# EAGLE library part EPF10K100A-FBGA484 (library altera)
EPF10K100 FLEX 10K family
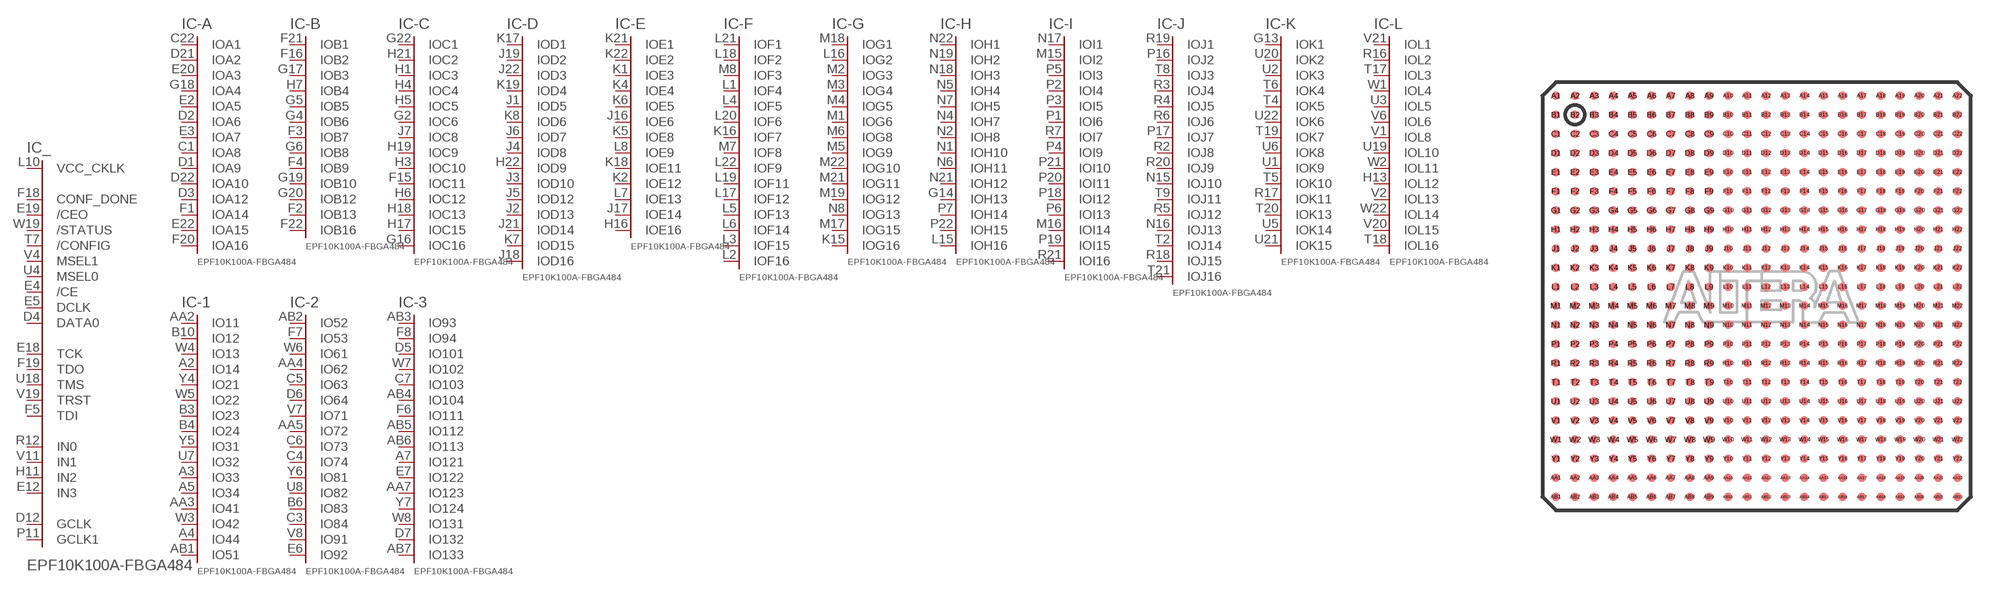
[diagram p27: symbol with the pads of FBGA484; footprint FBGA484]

Designator prefix IC; gates _=100B484C -A=A484 -B=B484 -C=C484 -D=D484 -E=E484 -F=F484 -G=G484 -H=H484 -I=I484 -J=J484 -K=K484 -L=L484 -1=IO51 -2=IO92 -3=IO133 -4=IO173 -5=IO214 -6=IO254 -7=IO302 -8=IO353 -9=IO401 -10=IO443 -11=IO483 -12=IO524 G1=GND G2=GND G3=GND G4=GND G5=GND G6=GND G7=GND G8=GND G9=GND G10=GND G11=GND G12=GND G13=GND G14=GND G15=GND G16=GND G17=GND G18=GND G19=GND G20=GND G21=GND G22=GND G23=GND G24=GND G25=GND G26=GND G27=GND G28=GND G29=GND G30=GND G31=GND G32=GND G33=GND G34=GND G35=GND G36=GND G37=GND G38=GND G39=GND G40=GND G41=GND G42=GND G43=GND G44=GND G45=GND G46=GND G47=GND G48=GND G49=GND V1=VCCINT V2=VCCINT V3=VCCINT V4=VCCINT V5=VCCINT V6=VCCINT V7=VCCINT V8=VCCINT V9=VCCINT V10=VCCINT V11=VCCINT V12=VCCINT V13=VCCINT V14=VCCINT V15=VCCINT V16=VCCINT V17=VCCINT V18=VCCINT V19=VCCINT V20=VCCINT V21=VCCINT V22=VCCINT VO1=VCCIO VO2=VCCIO VO3=VCCIO VO4=VCCIO VO5=VCCIO VO6=VCCIO VO7=VCCIO VO8=VCCIO VO9=VCCIO VO10=VCCIO VO11=VCCIO VO12=VCCIO VO13=VCCIO VO14=VCCIO VO15=VCCIO VO16=VCCIO VO17=VCCIO VO18=VCCIO VO19=VCCIO VO20=VCCIO VO21=VCCIO VO22=VCCIO VO23=VCCIO VO24=VCCIO VO25=VCCIO VO26=VCCIO VO27=VCCIO VO28=VCCIO VO29=VCCIO

## EPF10K100A-FBGA484 (MPN: EPF10K100AFC484-1; OC_FARNELL: unknown; OC_NEWARK: 51R8791)  [FBGA484]
A1  G6:GND  pwr
A2  -1:IO14
A3  -1:IO33
A4  -1:IO44
A5  -1:IO34
A6  VO2:VCCIO  pwr
A7  -3:IO121
A8  G7:GND  pwr
A9  -5:IO194
A10  -6:IO234
A11  -7:IO263
A12  -7:IO284
A13  VO3:VCCIO  pwr
A14  -9:IO363
A15  -9:IO381
A16  -10:IO432
A17  -10:IO434
A18  -10:IO441
A19  -11:IO452
A20  -11:IO471
A21  -12:IO501
A22  G8:GND  pwr
AA1  G1:GND  pwr
AA2  -1:IO11
AA3  -1:IO41
AA4  -2:IO62
AA5  -2:IO72
AA6  G2:GND  pwr
AA7  -3:IO123
AA8  -4:IO153
AA9  -5:IO181
AA10  -6:IO223
AA11  -7:IO264
AA12  V1:VCC  pwr
AA13  -8:IO313
AA14  -8:IO341
AA15  -9:IO394
AA16  -10:IO413
AA17  -11:IO451
AA18  -11:IO481
AA19  -12:IO492
AA20  -12:IO511
AA21  -12:IO513
AA22  G3:GND  pwr
AB1  -1:IO51
AB2  -2:IO52
AB3  -3:IO93
AB4  -3:IO104
AB5  -3:IO112
AB6  -3:IO113
AB7  -3:IO133
AB8  -4:IO151
AB9  -5:IO191
AB10  -6:IO231
AB11  G4:GND  pwr
AB12  -7:IO271
AB13  VO1:VCCIO  pwr
AB14  -8:IO331
AB15  -9:IO373
AB16  G5:GND  pwr
AB17  -10:IO442
AB18  -11:IO463
AB19  -11:IO472
AB20  -11:IO483
AB21  -12:IO504
AB22  -12:IO521
B1  G9:GND  pwr
B2  G10:GND  pwr
B3  -1:IO23
B4  -1:IO24
B5  VO4:VCCIO  pwr
B6  -2:IO83
B7  -4:IO134
B8  -4:IO164
B9  -5:IO192
B10  -1:IO12
B11  -6:IO252
B12  -7:IO282
B13  -8:IO323
B14  -9:IO364
B15  -9:IO371
B16  -10:IO412
B17  G11:GND  pwr
B18  -11:IO461
B19  -12:IO494
B20  -12:IO514
B21  G12:GND  pwr
B22  G13:GND  pwr
C1  -A:IOA8
C2  G14:GND  pwr
C3  -2:IO84
C4  -2:IO74
C5  -2:IO63
C6  -2:IO73
C7  -3:IO103
C8  -4:IO154
C9  -5:IO182
C10  -5:IO212
C11  V2:VCC  pwr
C12  -7:IO274
C13  -8:IO312
C14  -9:IO354
C15  V3:VCC  pwr
C16  -10:IO424
C17  -11:IO444
C18  -11:IO482
C19  -12:IO524
C20  -11:IO464
C21  G15:GND  pwr
C22  -A:IOA1
D1  -A:IOA9
D2  -A:IOA6
D3  -A:IOA12
D4  _:DATA0  in
D5  -3:IO101
D6  -2:IO64
D7  -3:IO132
D8  -4:IO142
D9  -5:IO184
D10  -6:IO221
D11  -6:IO253
D12  _:GCLK  in
D13  -8:IO333
D14  -8:IO353
D15  -9:IO391
D16  -10:IO423
D17  -11:IO474
D18  -12:IO512
D19  -12:IO522
D20  -11:IO454
D21  -A:IOA2
D22  -A:IOA10
E1  VO5:VCCIO  pwr
E2  -A:IOA5
E3  -A:IOA7
E4  _:/CE  in
E5  _:DCLK  in
E6  -2:IO92
E7  -3:IO122
E8  -4:IO152
E9  -5:IO201
E10  -6:IO222
E11  -6:IO242
E12  _:IN3  in
E13  -8:IO344
E14  -9:IO374
E15  -10:IO404
E16  -10:IO411
E17  -12:IO502
E18  _:TCK
E19  _:/CEO  in
E20  -A:IOA3
E21  G16:GND  pwr
E22  -A:IOA15
F1  -A:IOA14
F2  -B:IOB13
F3  -B:IOB7
F4  -B:IOB9
F5  _:TDI
F6  -3:IO111
F7  -2:IO53
F8  -3:IO94
F9  -5:IO174
F10  -5:IO214
F11  -6:IO232
F12  -7:IO272
F13  -8:IO343
F14  -9:IO384
F15  -C:IOC11
F16  -B:IOB2
F17  -12:IO491
F18  _:CONF_DONE  in
F19  _:TDO
F20  -A:IOA16
F21  -B:IOB1
F22  -B:IOB16
G1  VO6:VCCIO  pwr
G2  -C:IOC6
G3  G17:GND  pwr
G4  -B:IOB6
G5  -B:IOB5
G6  -B:IOB8
G7  -4:IO143
G8  -4:IO171
G9  -4:IO162
G10  -6:IO244
G11  -7:IO261
G12  -7:IO294
G13  -K:IOK1
G14  -H:IOH13
G15  VO7:VCCIO  pwr
G16  -C:IOC16
G17  -B:IOB3
G18  -A:IOA4
G19  -B:IOB10
G20  -B:IOB12
G21  G18:GND  pwr
G22  -C:IOC1
H1  -C:IOC3
H2  G19:GND  pwr
H3  -C:IOC10
H4  -C:IOC4
H5  -C:IOC5
H6  -C:IOC12
H7  -B:IOB4
H8  G20:GND  pwr
H9  VO8:VCCIO  pwr
H10  -5:IO204
H11  _:IN2  in
H12  -7:IO302
H13  -L:IOL12
H14  V4:VCC  pwr
H15  G21:GND  pwr
H16  -E:IOE16
H17  -C:IOC15
H18  -C:IOC13
H19  -C:IOC9
H20  VO9:VCCIO  pwr
H21  -C:IOC2
H22  -D:IOD9
J1  -D:IOD5
J2  -D:IOD13
J3  -D:IOD10
J4  -D:IOD8
J5  -D:IOD12
J6  -D:IOD7
J7  -C:IOC8
J8  V5:VCC  pwr
J9  G22:GND  pwr
J10  V6:VCC  pwr
J11  VO10:VCCIO  pwr
J12  V7:VCC  pwr
J13  VO11:VCCIO  pwr
J14  G23:GND  pwr
J15  V8:VCC  pwr
J16  -E:IOE6
J17  -E:IOE14
J18  -D:IOD16
J19  -D:IOD2
J20  G24:GND  pwr
J21  -D:IOD14
J22  -D:IOD3
K1  -E:IOE3
K2  -E:IOE12
K3  G25:GND  pwr
K4  -E:IOE4
K5  -E:IOE8
K6  -E:IOE5
K7  -D:IOD15
K8  -D:IOD6
K9  VO12:VCCIO  pwr
K10  G26:GND  pwr
K11  VO13:VCCIO  pwr
K12  G27:GND  pwr
K13  G28:GND  pwr
K14  VO14:VCCIO  pwr
K15  -G:IOG16
K16  -F:IOF7
K17  -D:IOD1
K18  -E:IOE11
K19  -D:IOD4
K20  VO15:VCCIO  pwr
K21  -E:IOE1
K22  -E:IOE2
L1  -F:IOF4
L2  -F:IOF16
L3  -F:IOF15
L4  -F:IOF5
L5  -F:IOF13
L6  -F:IOF14
L7  -E:IOE13
L8  -E:IOE9
L9  V9:VCC  pwr
L10  _:VCC_CKLK  pas
L11  G29:GND  pwr
L12  G30:GND  pwr
L13  V10:VCC  pwr
L14  VO16:VCCIO  pwr
L15  -H:IOH16
L16  -G:IOG2
L17  -F:IOF12
L18  -F:IOF2
L19  -F:IOF11
L20  -F:IOF6
L21  -F:IOF1
L22  -F:IOF9
M1  -G:IOG6
M2  -G:IOG3
M3  -G:IOG4
M4  -G:IOG5
M5  -G:IOG9
M6  -G:IOG8
M7  -F:IOF8
M8  -F:IOF3
M9  VO17:VCCIO  pwr
M10  V11:VCC  pwr
M11  G31:GND  pwr
M12  G32:GND  pwr
M13  V12:VCC  pwr
M14  V13:VCC  pwr
M15  -I:IOI2
M16  -I:IOI14
M17  -G:IOG15
M18  -G:IOG1
M19  -G:IOG12
M20  G33:GND  pwr
M21  -G:IOG11
M22  -G:IOG10
N1  -H:IOH10
N2  -H:IOH8
N3  VO18:VCCIO  pwr
N4  -H:IOH7
N5  -H:IOH4
N6  -H:IOH11
N7  -H:IOH5
N8  -G:IOG13
N9  VO19:VCCIO  pwr
N10  G34:GND  pwr
N11  VO20:VCCIO  pwr
N12  V14:VCC  pwr
N13  G35:GND  pwr
N14  VO21:VCCIO  pwr
N15  -J:IOJ10
N16  -J:IOJ13
N17  -I:IOI1
N18  -H:IOH3
N19  -H:IOH2
N20  VO22:VCCIO  pwr
N21  -H:IOH12
N22  -H:IOH1
P1  -I:IOI6
P2  -I:IOI4
P3  -I:IOI5
P4  -I:IOI9
P5  -I:IOI3
P6  -I:IOI13
P7  -H:IOH14
P8  V15:VCC  pwr
P9  G36:GND  pwr
P10  V16:VCC  pwr
P11  _:GCLK1  in
P12  V17:VCC  pwr
P13  VO23:VCCIO  pwr
P14  G37:GND  pwr
P15  V18:VCC  pwr
P16  -J:IOJ2
P17  -J:IOJ7
P18  -I:IOI12
P19  -I:IOI15
P20  -I:IOI11
P21  -I:IOI10
P22  -H:IOH15
R1  VO24:VCCIO  pwr
R2  -J:IOJ8
R3  -J:IOJ4
R4  -J:IOJ5
R5  -J:IOJ12
R6  -J:IOJ6
R7  -I:IOI7
R8  G38:GND  pwr
R9  VO25:VCCIO  pwr
R10  -4:IO161
R11  -4:IO173
R12  _:IN0  in
R13  -7:IO281
R14  V19:VCC  pwr
R15  G39:GND  pwr
R16  -L:IOL2
R17  -K:IOK11
R18  -J:IOJ15
R19  -J:IOJ1
R20  -J:IOJ9
R21  -I:IOI16
R22  G40:GND  pwr
T1  G41:GND  pwr
T2  -J:IOJ14
T3  VO26:VCCIO  pwr
T4  -K:IOK5
T5  -K:IOK10
T6  -K:IOK4
T7  _:/CONFIG  in
T8  -J:IOJ3
T9  -J:IOJ11
T10  -4:IO163
T11  -5:IO213
T12  -6:IO233
T13  -8:IO303
T14  -8:IO321
T15  VO27:VCCIO  pwr
T16  -9:IO392
T17  -L:IOL3
T18  -L:IOL16
T19  -K:IOK7
T20  -K:IOK13
T21  -J:IOJ16
T22  VO28:VCCIO  pwr
U1  -K:IOK9
U2  -K:IOK3
U3  -L:IOL5
U4  _:MSEL0  in
U5  -K:IOK14
U6  -K:IOK8
U7  -1:IO32
U8  -2:IO82
U9  -4:IO141
U10  -5:IO203
U11  -6:IO241
U12  -6:IO243
U13  -7:IO293
U14  -8:IO351
U15  -9:IO361
U16  -9:IO401
U17  -11:IO462
U18  _:TMS
U19  -L:IOL10
U20  -K:IOK2
U21  -K:IOK15
U22  -K:IOK6
V1  -L:IOL8
V2  -L:IOL13
V3  G42:GND  pwr
V4  _:MSEL1  in
V5  V20:VCC  pwr
V6  -L:IOL6
V7  -2:IO71
V8  -2:IO91
V9  -4:IO144
V10  -5:IO202
V11  _:IN1  in
V12  -6:IO254
V13  -7:IO291
V14  -8:IO322
V15  -9:IO372
V16  -10:IO402
V17  -10:IO421
V18  -11:IO453
V19  _:TRST
V20  -L:IOL15
V21  -L:IOL1
V22  VO29:VCCIO  pwr
W1  -L:IOL4
W2  -L:IOL11
W3  -1:IO42
W4  -1:IO13
W5  -1:IO22
W6  -2:IO61
W7  -3:IO102
W8  -3:IO131
W9  -5:IO183
W10  -6:IO224
W11  G43:GND  pwr
W12  -7:IO273
W13  -7:IO301
W14  -8:IO332
W15  -9:IO362
W16  -10:IO414
W17  -10:IO431
W18  -11:IO473
W19  _:/STATUS  in
W20  G44:GND  pwr
W21  V21:VCC  pwr
W22  -L:IOL14
Y1  G45:GND  pwr
Y2  G46:GND  pwr
Y3  G47:GND  pwr
Y4  -1:IO21
Y5  -1:IO31
Y6  -2:IO81
Y7  -3:IO124
Y8  V22:VCC  pwr
Y9  -4:IO172
Y10  -5:IO211
Y11  -6:IO251
Y12  -7:IO283
Y13  -8:IO311
Y14  -8:IO352
Y15  -9:IO383
Y16  -10:IO433
Y17  -10:IO443
Y18  -12:IO493
Y19  -12:IO503
Y20  -12:IO523
Y21  G48:GND  pwr
Y22  G49:GND  pwr

## Footprint FBGA484 (pad centres in mm)
Fine Ball Grid Array
smd 0.45 x 0.45: A1 -10.5,10.5; A2 -9.5,10.5; A3 -8.5,10.5; A4 -7.5,10.5; A5 -6.5,10.5; A6 -5.5,10.5; A7 -4.5,10.5; A8 -3.5,10.5; A9 -2.5,10.5; A10 -1.5,10.5; A11 -0.5,10.5; A12 0.5,10.5; A13 1.5,10.5; A14 2.5,10.5; A15 3.5,10.5; A16 4.5,10.5; A17 5.5,10.5; A18 6.5,10.5; A19 7.5,10.5; A20 8.5,10.5; A21 9.5,10.5; A22 10.5,10.5; AA1 -10.5,-9.5; AA2 -9.5,-9.5; AA3 -8.5,-9.5; AA4 -7.5,-9.5; AA5 -6.5,-9.5; AA6 -5.5,-9.5; AA7 -4.5,-9.5; AA8 -3.5,-9.5; AA9 -2.5,-9.5; AA10 -1.5,-9.5; AA11 -0.5,-9.5; AA12 0.5,-9.5; AA13 1.5,-9.5; AA14 2.5,-9.5; AA15 3.5,-9.5; AA16 4.5,-9.5; AA17 5.5,-9.5; AA18 6.5,-9.5; AA19 7.5,-9.5; AA20 8.5,-9.5; AA21 9.5,-9.5; AA22 10.5,-9.5; AB1 -10.5,-10.5; AB2 -9.5,-10.5; AB3 -8.5,-10.5; AB4 -7.5,-10.5; AB5 -6.5,-10.5; AB6 -5.5,-10.5; AB7 -4.5,-10.5; AB8 -3.5,-10.5; AB9 -2.5,-10.5; AB10 -1.5,-10.5; AB11 -0.5,-10.5; AB12 0.5,-10.5; AB13 1.5,-10.5; AB14 2.5,-10.5; AB15 3.5,-10.5; AB16 4.5,-10.5; AB17 5.5,-10.5; AB18 6.5,-10.5; AB19 7.5,-10.5; AB20 8.5,-10.5; AB21 9.5,-10.5; AB22 10.5,-10.5; B1 -10.5,9.5; B2 -9.5,9.5; B3 -8.5,9.5; B4 -7.5,9.5; B5 -6.5,9.5; B6 -5.5,9.5; B7 -4.5,9.5; B8 -3.5,9.5; B9 -2.5,9.5; B10 -1.5,9.5; B11 -0.5,9.5; B12 0.5,9.5; B13 1.5,9.5; B14 2.5,9.5; B15 3.5,9.5; B16 4.5,9.5; B17 5.5,9.5; B18 6.5,9.5; B19 7.5,9.5; B20 8.5,9.5; B21 9.5,9.5; B22 10.5,9.5; C1 -10.5,8.5; C2 -9.5,8.5; C3 -8.5,8.5; C4 -7.5,8.5; C5 -6.5,8.5; C6 -5.5,8.5; C7 -4.5,8.5; C8 -3.5,8.5; C9 -2.5,8.5; C10 -1.5,8.5; C11 -0.5,8.5; C12 0.5,8.5; C13 1.5,8.5; C14 2.5,8.5; C15 3.5,8.5; C16 4.5,8.5; C17 5.5,8.5; C18 6.5,8.5; C19 7.5,8.5; C20 8.5,8.5; C21 9.5,8.5; C22 10.5,8.5; D1 -10.5,7.5; D2 -9.5,7.5; D3 -8.5,7.5; D4 -7.5,7.5; D5 -6.5,7.5; D6 -5.5,7.5; D7 -4.5,7.5; D8 -3.5,7.5; D9 -2.5,7.5; D10 -1.5,7.5; D11 -0.5,7.5; D12 0.5,7.5; D13 1.5,7.5; D14 2.5,7.5; D15 3.5,7.5; D16 4.5,7.5; D17 5.5,7.5; D18 6.5,7.5; D19 7.5,7.5; D20 8.5,7.5; D21 9.5,7.5; D22 10.5,7.5; E1 -10.5,6.5; E2 -9.5,6.5; E3 -8.5,6.5; E4 -7.5,6.5; E5 -6.5,6.5; E6 -5.5,6.5; E7 -4.5,6.5; E8 -3.5,6.5; E9 -2.5,6.5; E10 -1.5,6.5; E11 -0.5,6.5; E12 0.5,6.5; E13 1.5,6.5; E14 2.5,6.5; E15 3.5,6.5; E16 4.5,6.5; E17 5.5,6.5; E18 6.5,6.5; E19 7.5,6.5; E20 8.5,6.5; E21 9.5,6.5; E22 10.5,6.5; F1 -10.5,5.5; F2 -9.5,5.5; F3 -8.5,5.5; F4 -7.5,5.5; F5 -6.5,5.5; F6 -5.5,5.5; F7 -4.5,5.5; F8 -3.5,5.5; F9 -2.5,5.5; F10 -1.5,5.5; F11 -0.5,5.5; F12 0.5,5.5; F13 1.5,5.5; F14 2.5,5.5; F15 3.5,5.5; F16 4.5,5.5; F17 5.5,5.5; F18 6.5,5.5; F19 7.5,5.5; F20 8.5,5.5; F21 9.5,5.5; F22 10.5,5.5; G1 -10.5,4.5; G2 -9.5,4.5; G3 -8.5,4.5; G4 -7.5,4.5; G5 -6.5,4.5; G6 -5.5,4.5; G7 -4.5,4.5; G8 -3.5,4.5; G9 -2.5,4.5; G10 -1.5,4.5; G11 -0.5,4.5; G12 0.5,4.5; G13 1.5,4.5; G14 2.5,4.5; G15 3.5,4.5; G16 4.5,4.5; G17 5.5,4.5; G18 6.5,4.5; G19 7.5,4.5; G20 8.5,4.5; G21 9.5,4.5; G22 10.5,4.5; H1 -10.5,3.5; H2 -9.5,3.5; H3 -8.5,3.5; H4 -7.5,3.5; H5 -6.5,3.5; H6 -5.5,3.5; H7 -4.5,3.5; H8 -3.5,3.5; H9 -2.5,3.5; H10 -1.5,3.5; H11 -0.5,3.5; H12 0.5,3.5; H13 1.5,3.5; H14 2.5,3.5; H15 3.5,3.5; H16 4.5,3.5; H17 5.5,3.5; H18 6.5,3.5; H19 7.5,3.5; H20 8.5,3.5; H21 9.5,3.5; H22 10.5,3.5; J1 -10.5,2.5; J2 -9.5,2.5; J3 -8.5,2.5; J4 -7.5,2.5; J5 -6.5,2.5; J6 -5.5,2.5; J7 -4.5,2.5; J8 -3.5,2.5; J9 -2.5,2.5; J10 -1.5,2.5; J11 -0.5,2.5; J12 0.5,2.5; J13 1.5,2.5; J14 2.5,2.5; J15 3.5,2.5; J16 4.5,2.5; J17 5.5,2.5; J18 6.5,2.5; J19 7.5,2.5; J20 8.5,2.5; J21 9.5,2.5; J22 10.5,2.5; K1 -10.5,1.5; K2 -9.5,1.5; K3 -8.5,1.5; K4 -7.5,1.5; K5 -6.5,1.5; K6 -5.5,1.5; K7 -4.5,1.5; K8 -3.5,1.5; K9 -2.5,1.5; K10 -1.5,1.5; K11 -0.5,1.5; K12 0.5,1.5; K13 1.5,1.5; K14 2.5,1.5; K15 3.5,1.5; K16 4.5,1.5; K17 5.5,1.5; K18 6.5,1.5; K19 7.5,1.5; K20 8.5,1.5; K21 9.5,1.5; K22 10.5,1.5; L1 -10.5,0.5; L2 -9.5,0.5; L3 -8.5,0.5; L4 -7.5,0.5; L5 -6.5,0.5; L6 -5.5,0.5; L7 -4.5,0.5; L8 -3.5,0.5; L9 -2.5,0.5; L10 -1.5,0.5; L11 -0.5,0.5; L12 0.5,0.5; L13 1.5,0.5; L14 2.5,0.5; L15 3.5,0.5; L16 4.5,0.5; L17 5.5,0.5; L18 6.5,0.5; L19 7.5,0.5; L20 8.5,0.5; L21 9.5,0.5; L22 10.5,0.5; M1 -10.5,-0.5; M2 -9.5,-0.5; M3 -8.5,-0.5; M4 -7.5,-0.5; M5 -6.5,-0.5; M6 -5.5,-0.5; M7 -4.5,-0.5; M8 -3.5,-0.5; M9 -2.5,-0.5; M10 -1.5,-0.5; M11 -0.5,-0.5; M12 0.5,-0.5; M13 1.5,-0.5; M14 2.5,-0.5; M15 3.5,-0.5; M16 4.5,-0.5; M17 5.5,-0.5; M18 6.5,-0.5; M19 7.5,-0.5; M20 8.5,-0.5; M21 9.5,-0.5; M22 10.5,-0.5; N1 -10.5,-1.5; N2 -9.5,-1.5; N3 -8.5,-1.5; N4 -7.5,-1.5; N5 -6.5,-1.5; N6 -5.5,-1.5; N7 -4.5,-1.5; N8 -3.5,-1.5; N9 -2.5,-1.5; N10 -1.5,-1.5; N11 -0.5,-1.5; N12 0.5,-1.5; N13 1.5,-1.5; N14 2.5,-1.5; N15 3.5,-1.5; N16 4.5,-1.5; N17 5.5,-1.5; N18 6.5,-1.5; N19 7.5,-1.5; N20 8.5,-1.5; N21 9.5,-1.5; N22 10.5,-1.5; P1 -10.5,-2.5; P2 -9.5,-2.5; P3 -8.5,-2.5; P4 -7.5,-2.5; P5 -6.5,-2.5; P6 -5.5,-2.5; P7 -4.5,-2.5; P8 -3.5,-2.5; P9 -2.5,-2.5; P10 -1.5,-2.5; P11 -0.5,-2.5; P12 0.5,-2.5; P13 1.5,-2.5; P14 2.5,-2.5; P15 3.5,-2.5; P16 4.5,-2.5; P17 5.5,-2.5; P18 6.5,-2.5; P19 7.5,-2.5; P20 8.5,-2.5; P21 9.5,-2.5; P22 10.5,-2.5; R1 -10.5,-3.5; R2 -9.5,-3.5; R3 -8.5,-3.5; R4 -7.5,-3.5; R5 -6.5,-3.5; R6 -5.5,-3.5; R7 -4.5,-3.5; R8 -3.5,-3.5; R9 -2.5,-3.5; R10 -1.5,-3.5; R11 -0.5,-3.5; R12 0.5,-3.5; R13 1.5,-3.5; R14 2.5,-3.5; R15 3.5,-3.5; R16 4.5,-3.5; R17 5.5,-3.5; R18 6.5,-3.5; R19 7.5,-3.5; R20 8.5,-3.5; R21 9.5,-3.5; R22 10.5,-3.5; T1 -10.5,-4.5; T2 -9.5,-4.5; T3 -8.5,-4.5; T4 -7.5,-4.5; T5 -6.5,-4.5; T6 -5.5,-4.5; T7 -4.5,-4.5; T8 -3.5,-4.5; T9 -2.5,-4.5; T10 -1.5,-4.5; T11 -0.5,-4.5; T12 0.5,-4.5; T13 1.5,-4.5; T14 2.5,-4.5; T15 3.5,-4.5; T16 4.5,-4.5; T17 5.5,-4.5; T18 6.5,-4.5; T19 7.5,-4.5; T20 8.5,-4.5; T21 9.5,-4.5; T22 10.5,-4.5; U1 -10.5,-5.5; U2 -9.5,-5.5; U3 -8.5,-5.5; U4 -7.5,-5.5; U5 -6.5,-5.5; U6 -5.5,-5.5; U7 -4.5,-5.5; U8 -3.5,-5.5; U9 -2.5,-5.5; U10 -1.5,-5.5; U11 -0.5,-5.5; U12 0.5,-5.5; U13 1.5,-5.5; U14 2.5,-5.5; U15 3.5,-5.5; U16 4.5,-5.5; U17 5.5,-5.5; U18 6.5,-5.5; U19 7.5,-5.5; U20 8.5,-5.5; U21 9.5,-5.5; U22 10.5,-5.5; V1 -10.5,-6.5; V2 -9.5,-6.5; V3 -8.5,-6.5; V4 -7.5,-6.5; V5 -6.5,-6.5; V6 -5.5,-6.5; V7 -4.5,-6.5; V8 -3.5,-6.5; V9 -2.5,-6.5; V10 -1.5,-6.5; V11 -0.5,-6.5; V12 0.5,-6.5; V13 1.5,-6.5; V14 2.5,-6.5; V15 3.5,-6.5; V16 4.5,-6.5; V17 5.5,-6.5; V18 6.5,-6.5; V19 7.5,-6.5; V20 8.5,-6.5; V21 9.5,-6.5; V22 10.5,-6.5; W1 -10.5,-7.5; W2 -9.5,-7.5; W3 -8.5,-7.5; W4 -7.5,-7.5; W5 -6.5,-7.5; W6 -5.5,-7.5; W7 -4.5,-7.5; W8 -3.5,-7.5; W9 -2.5,-7.5; W10 -1.5,-7.5; W11 -0.5,-7.5; W12 0.5,-7.5; W13 1.5,-7.5; W14 2.5,-7.5; W15 3.5,-7.5; W16 4.5,-7.5; W17 5.5,-7.5; W18 6.5,-7.5; W19 7.5,-7.5; W20 8.5,-7.5; W21 9.5,-7.5; W22 10.5,-7.5; Y1 -10.5,-8.5; Y2 -9.5,-8.5; Y3 -8.5,-8.5; Y4 -7.5,-8.5; Y5 -6.5,-8.5; Y6 -5.5,-8.5; Y7 -4.5,-8.5; Y8 -3.5,-8.5; Y9 -2.5,-8.5; Y10 -1.5,-8.5; Y11 -0.5,-8.5; Y12 0.5,-8.5; Y13 1.5,-8.5; Y14 2.5,-8.5; Y15 3.5,-8.5; Y16 4.5,-8.5; Y17 5.5,-8.5; Y18 6.5,-8.5; Y19 7.5,-8.5; Y20 8.5,-8.5; Y21 9.5,-8.5; Y22 10.5,-8.5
